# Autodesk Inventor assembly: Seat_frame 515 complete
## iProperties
Shininess: 20.0
Length Units: 11269
Angle Units: 11279
Time Units: 11290
Mass Units: 11283
Length Display Precision: 3
Angle Display Precision: 2
Created: 2001-04
Part Number: Seat_frame 515 complete
Document SubType Name: Baugruppe
Designer: dl
Density: 0.0
Volumn: 0.0
Area: 0.0
PropertySet Name: Model Information
Control State: 0
Master: False
Checked Out: False
Author: dl
